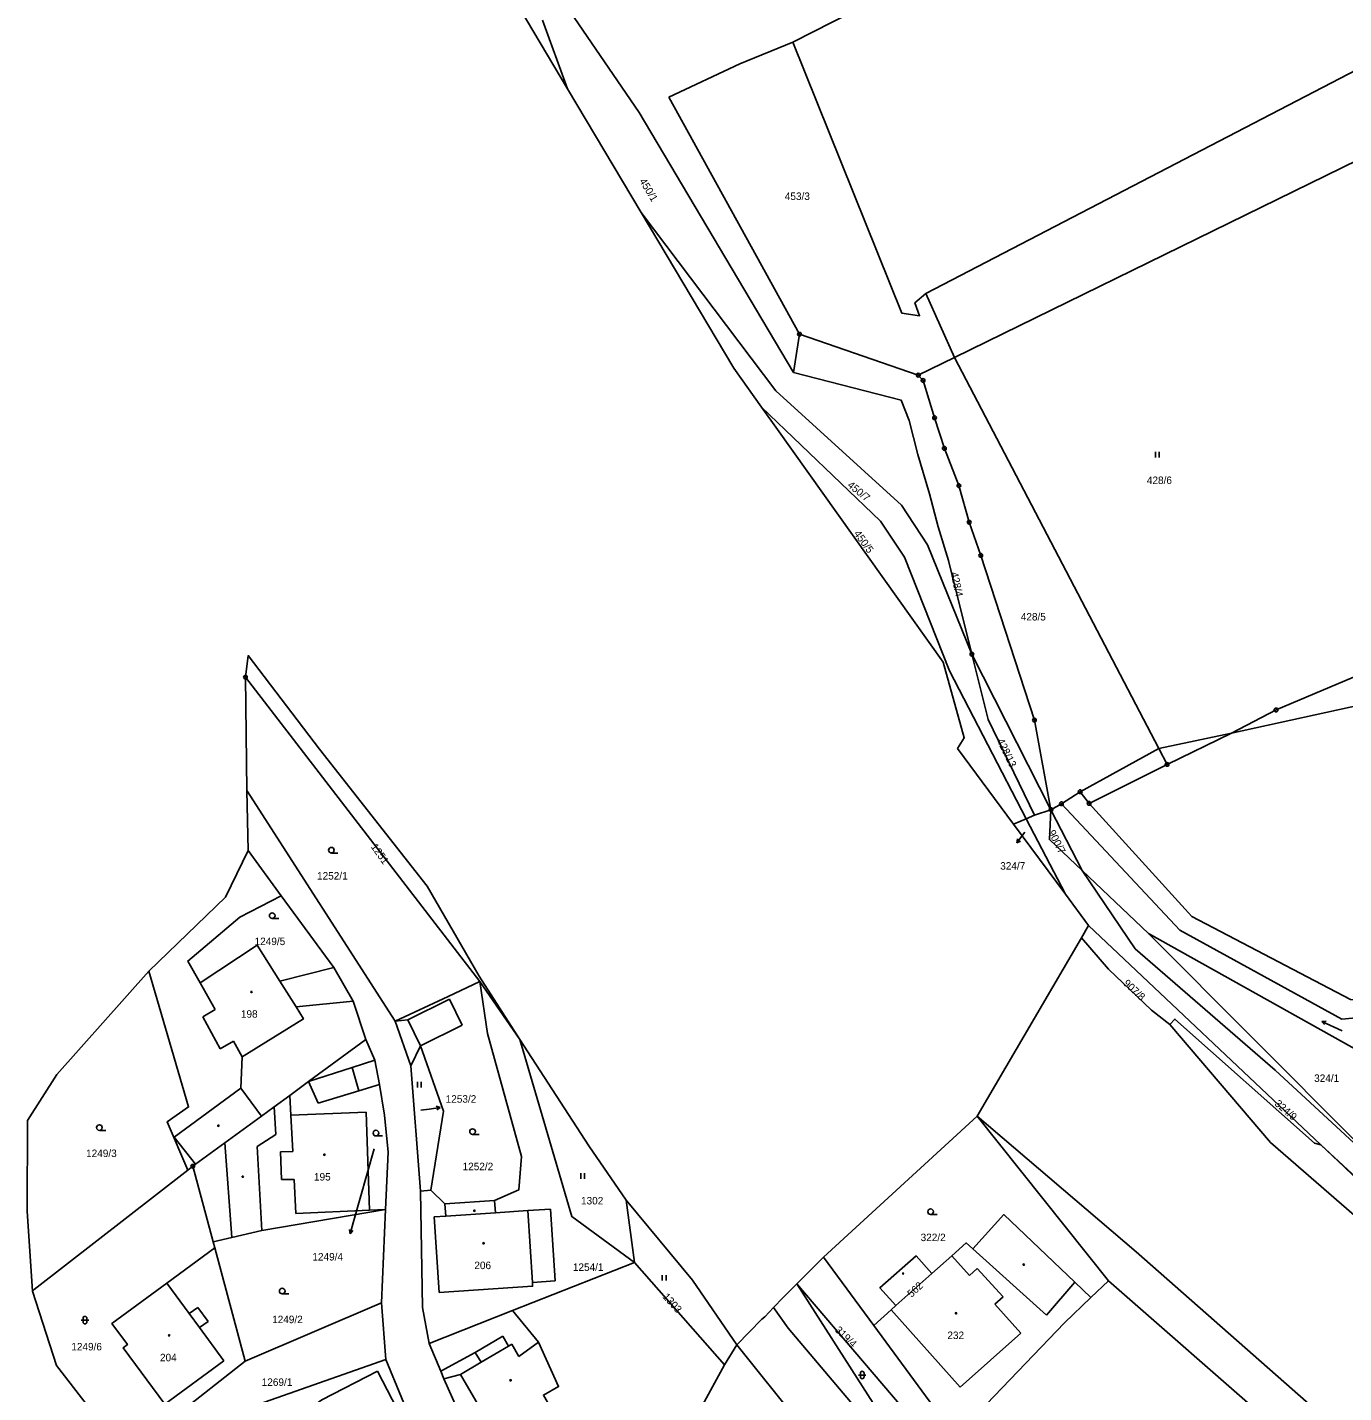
# Model space of a CAD drawing. Extents: x -745926 to -742978, y -968282 to -965689.
# Drawn here: x -745352.5 to -745176.7, y -966916.9 to -966734.5 of the extents above; entities that cross this region are included whole.
import ezdxf

# ---------------------------------------------------------------- set-up
doc = ezdxf.new("R2010")
doc.units = 0
for name, color, linetype in [('Hranice parcel', 7, 'Continuous'), ('Parcelní čísla', 7, 'Continuous'), ('Pop  PČ popisy', 7, 'Continuous'), ('Poz předměty', 7, 'Continuous'), ('Vnitřní kresba', 7, 'Continuous'), ('Značky bodu BP', 7, 'Continuous'), ('Značky budov', 7, 'Continuous'), ('Značky kultur', 7, 'Continuous')]:
    doc.layers.add(name, color=color, linetype=linetype)

msp = doc.modelspace()

# ---------------------------------------------------------------- linework, layer by layer
at = {"layer": 'Hranice parcel'}
for p, q in [((-745232.51, -966770.07), (-745145.82, -966725.01)), ((-745280.38, -966742.7), (-745289.63, -966727.14)), ((-745283.72, -966733.52), (-745280.38, -966742.7)), ((-745280.38, -966742.7), (-745270.55, -966759.22)), ((-745249.4, -966775.5), (-745266.84, -966743.81)), ((-745232.51, -966770.07), (-745228.69, -966778.6)), ((-745249.4, -966775.5), (-745250.2, -966780.6)), ((-745233.52, -966780.96), (-745249.4, -966775.5)), ((-745228.69, -966778.6), (-745233.52, -966780.96)), ((-745252.34, -966788.23), (-745254.48, -966785.22)), ((-745232.31, -966803.64), (-745226.36, -966818.23)), ((-745226.36, -966818.23), (-745215.8, -966839)), ((-745323.4, -966821.3), (-745292.08, -966861.94)), ((-745323.4, -966821.3), (-745323.2, -966836.46)), ((-745219.1, -966840.21), (-745229.35, -966820.44)), ((-745220.81, -966840.92), (-745228.28, -966830.83)), ((-745200.3, -966832.96), (-745210.7, -966838.16)), ((-745323.2, -966836.46), (-745303.39, -966867.27)), ((-745323.2, -966836.46), (-745323.04, -966844.47)), ((-745214.4, -966838.2), (-745211.9, -966836.6)), ((-745211.9, -966836.6), (-745210.7, -966838.16)), ((-745219.1, -966840.21), (-745218.01, -966839.75)), ((-745218.01, -966839.75), (-745215.8, -966839)), ((-745215.8, -966839), (-745214.4, -966838.2)), ((-745215.8, -966839), (-745211.62, -966847.14)), ((-745220.81, -966840.92), (-745219.1, -966840.21)), ((-745213.87, -966850.28), (-745220.81, -966840.92)), ((-745213.87, -966850.28), (-745219.1, -966840.21)), ((-745318.62, -966850.49), (-745323.04, -966844.47)), ((-745202.76, -966855.54), (-745211.62, -966847.14)), ((-745211.62, -966847.14), (-745204.57, -966857.59)), ((-745210.77, -966854.47), (-745213.87, -966850.28)), ((-745211.73, -966856.11), (-745225.67, -966879.96)), ((-745210.77, -966854.47), (-745211.73, -966856.11)), ((-745179.76, -966883.79), (-745210.77, -966854.47)), ((-745167.54, -966875.26), (-745202.76, -966855.54)), ((-745292.08, -966861.94), (-745286.75, -966869.71)), ((-745303.39, -966867.27), (-745301.3, -966873.2)), ((-745301.3, -966873.2), (-745300.03, -966889.97)), ((-745225.67, -966879.96), (-745246.2, -966898.77)), ((-745208.11, -966901.93), (-745225.67, -966879.96)), ((-745179.76, -966883.79), (-745180.6, -966883.53)), ((-745166.58, -966896), (-745179.76, -966883.79)), ((-745331.09, -966887.14), (-745330.43, -966886.63)), ((-745330.43, -966886.63), (-745327.71, -966896.73)), ((-745300.03, -966889.97), (-745298.65, -966889.82)), ((-745298.65, -966889.82), (-745296.74, -966891.65)), ((-745305.22, -966904.86), (-745304.68, -966892.41)), ((-745290.11, -966891.2), (-745296.74, -966891.65)), ((-745271.45, -966899.49), (-745272.52, -966891.18)), ((-745327.71, -966896.73), (-745327.5, -966897.54)), ((-745323.44, -966912.67), (-745327.5, -966897.54)), ((-745287.72, -966905.92), (-745271.45, -966899.49)), ((-745259.41, -966913.16), (-745271.45, -966899.49)), ((-745246.2, -966898.77), (-745249.76, -966902.34)), ((-745239.47, -966907.89), (-745246.2, -966898.77)), ((-745231.7, -966900.95), (-745236.51, -966905.25)), ((-745249.76, -966902.34), (-745237.49, -966921.45)), ((-745249.76, -966902.34), (-745234.53, -966920.19)), ((-745208.11, -966901.93), (-745210.46, -966904.18)), ((-745180.55, -966926.05), (-745208.11, -966901.93)), ((-745323.44, -966912.67), (-745305.22, -966904.86)), ((-745305.22, -966904.86), (-745304.66, -966912.43)), ((-745287.72, -966905.92), (-745298.84, -966910.32)), ((-745239.47, -966907.89), (-745228.55, -966922.71)), ((-745257.76, -966910.48), (-745259.41, -966913.16)), ((-745233, -966941.3), (-745257.76, -966910.48)), ((-745332.81, -966920.07), (-745323.44, -966912.67)), ((-745259.41, -966913.16), (-745274.6, -966940.8))]:
    msp.add_line(p, q, dxfattribs=at)
for points in [[(-745163.29, -966688.08), (-745207.73, -966714.8), (-745250.26, -966736.5)], [(-745250.2, -966780.6), (-745270.8, -966745.89), (-745287.59, -966721.28)], [(-745266.84, -966743.81), (-745257.34, -966739.37), (-745250.26, -966736.5)], [(-745250.26, -966736.5), (-745235.74, -966772.67), (-745233.34, -966773.02), (-745234, -966771.3), (-745232.51, -966770.07)], [(-745254.48, -966785.22), (-745258.18, -966780.03), (-745270.55, -966759.22)], [(-745270.55, -966759.22), (-745252.54, -966783.04), (-745235.77, -966798.31), (-745232.31, -966803.64)], [(-745200.3, -966832.96), (-745201.41, -966830.84), (-745228.69, -966778.6)], [(-745250.2, -966780.6), (-745235.8, -966784.3), (-745234.72, -966787), (-745233.57, -966791.57), (-745232.04, -966796.79), (-745230.89, -966801.2), (-745229.51, -966805.7), (-745226.36, -966818.23)], [(-745215.8, -966839), (-745218.01, -966827.04), (-745225.18, -966805.03), (-745226.72, -966800.61), (-745228.1, -966795.72), (-745230.04, -966790.74), (-745231.35, -966786.64), (-745232.89, -966781.66), (-745233.52, -966780.96)], [(-745229.35, -966820.44), (-745235.36, -966805.29), (-745238.55, -966800.45), (-745254.48, -966785.22)], [(-745228.28, -966830.83), (-745227.38, -966829.4), (-745230.21, -966819.31), (-745252.34, -966788.23)], [(-745286.75, -966869.71), (-745292.18, -966861.26), (-745299.11, -966849.23), (-745313.51, -966830.92), (-745323.01, -966818.42), (-745323.4, -966821.3)], [(-745226.36, -966818.23), (-745224.17, -966826.96), (-745218.01, -966839.75)], [(-745169.4, -966818.77), (-745185.74, -966825.68), (-745191.7, -966828.8), (-745200.3, -966832.96)], [(-745215.8, -966839), (-745216, -966843), (-745211.62, -966847.14)], [(-745214.4, -966838.2), (-745198.59, -966855.11), (-745176.97, -966866.98), (-745158.86, -966865.27)], [(-745210.7, -966838.16), (-745196.97, -966853.29), (-745175.81, -966864.35), (-745142.14, -966865.81), (-745134.77, -966866.14)], [(-745323.04, -966844.47), (-745326.06, -966850.68), (-745336.32, -966860.58)], [(-745321.26, -966879.92), (-745324, -966876.18), (-745323.82, -966872.03), (-745315.64, -966866.94), (-745316.64, -966865.35), (-745318.79, -966861.92), (-745321.82, -966857.1), (-745329.44, -966862.14), (-745331.1, -966859.23), (-745324.15, -966853.34), (-745318.62, -966850.49)], [(-745307.31, -966869.72), (-745309, -966864.6), (-745311.59, -966860.07), (-745318.62, -966850.49)], [(-745180.6, -966883.53), (-745199.24, -966866.97), (-745199.92, -966867.71), (-745202.37, -966865.76), (-745208.1, -966860.3), (-745211.73, -966856.11)], [(-745204.57, -966857.59), (-745185.85, -966873.79), (-745163.08, -966894.85), (-745158.2, -966898.34)], [(-745336.32, -966860.58), (-745348.59, -966874.36), (-745352.52, -966880.53)], [(-745336.32, -966860.58), (-745330.98, -966878.7), (-745333.83, -966880.68), (-745331.09, -966887.14)], [(-745303.39, -966867.27), (-745296.33, -966863.94), (-745292.08, -966861.94)], [(-745290.11, -966891.2), (-745286.86, -966889.77), (-745286.5, -966885.31), (-745291.07, -966868.91), (-745292.08, -966861.94)], [(-745307.31, -966869.72), (-745314.98, -966875.33), (-745317.48, -966877.16)], [(-745304.68, -966892.41), (-745304.34, -966884.77), (-745304.83, -966879.81), (-745305.5, -966875.7), (-745306.13, -966872.47), (-745307.31, -966869.72)], [(-745301.3, -966873.2), (-745299.99, -966870.53), (-745296.94, -966879.27), (-745298.65, -966889.82)], [(-745271.45, -966899.49), (-745279.8, -966893.35), (-745286.75, -966869.71)], [(-745272.52, -966891.18), (-745277.53, -966883.91), (-745286.75, -966869.71)], [(-745317.48, -966877.16), (-745319.56, -966878.68), (-745321.26, -966879.92)], [(-745304.68, -966892.41), (-745306.84, -966892.5), (-745307.29, -966879.41), (-745317.34, -966879.81), (-745317.48, -966877.16)], [(-745321.26, -966879.92), (-745326.15, -966883.5), (-745330.08, -966886.36), (-745330.43, -966886.63)], [(-745352.52, -966880.53), (-745352.53, -966892.61), (-745351.83, -966903.32)], [(-745140.63, -966918.06), (-745162.42, -966900.43), (-745176.65, -966886.73), (-745179.76, -966883.79)], [(-745351.83, -966903.32), (-745351.61, -966903.1), (-745331.09, -966887.14)], [(-745300.03, -966889.97), (-745299.73, -966905.49), (-745298.84, -966910.32)], [(-745327.71, -966896.73), (-745325.19, -966896.14), (-745321.2, -966895.19), (-745304.68, -966892.41)], [(-745296.74, -966891.65), (-745296.63, -966893.29), (-745298.18, -966893.4), (-745297.5, -966903.49), (-745285.04, -966902.65), (-745285.07, -966902.15), (-745285.67, -966892.55), (-745290, -966892.85), (-745290.11, -966891.2)], [(-745257.76, -966910.48), (-745263.7, -966901.85), (-745272.52, -966891.18)], [(-745210.46, -966904.18), (-745212.61, -966902.13), (-745222.1, -966893.08), (-745226.23, -966897.66), (-745227.12, -966896.86), (-745229.05, -966898.59), (-745231.7, -966900.95)], [(-745327.5, -966897.54), (-745333.89, -966902.25), (-745341.22, -966907.64), (-745339.15, -966910.46), (-745339.71, -966910.87), (-745334.15, -966918.42), (-745332.81, -966920.07)], [(-745236.51, -966905.25), (-745238.64, -966902.87), (-745233.8, -966898.61), (-745231.7, -966900.95)], [(-745351.83, -966903.32), (-745348.62, -966913.24), (-745339.35, -966925.23)], [(-745249.76, -966902.34), (-745251.2, -966903.8), (-745251.55, -966904.17), (-745252.87, -966905.5), (-745254, -966906.76), (-745254.4, -966907.06), (-745257.76, -966910.48)], [(-745236.51, -966905.25), (-745237.13, -966905.8), (-745239.47, -966907.89)], [(-745228.55, -966922.71), (-745214, -966907.56), (-745210.46, -966904.18)], [(-745296.89, -966915.01), (-745294.69, -966914.43), (-745289.63, -966923.08), (-745282.55, -966918.97), (-745283.6, -966917.2), (-745281.57, -966916.07), (-745284.25, -966910.15), (-745287.72, -966905.92)], [(-745298.84, -966910.32), (-745297.3, -966914), (-745296.89, -966915.01)], [(-745304.66, -966912.43), (-745325.66, -966919.82), (-745328.98, -966921.69), (-745330.87, -966923.57)], [(-745297.73, -966925.14), (-745300.47, -966922.59), (-745304.66, -966912.43)], [(-745305.75, -966913.99), (-745313.18, -966917.83), (-745314.95, -966919.14), (-745318.93, -966921.21), (-745315.33, -966927.53), (-745311.51, -966925.53), (-745307.15, -966926.1), (-745301.15, -966922.87), (-745305.75, -966913.99)], [(-745296.89, -966915.01), (-745295, -966919.3), (-745292.7, -966924.7), (-745284.5, -966933.2), (-745279.6, -966937.3), (-745274.6, -966940.8)]]:
    msp.add_lwpolyline(points, dxfattribs=at)
at = {"layer": 'Pop  PČ popisy'}
for p, q in [((-745219.47, -966842.23), (-745220.35, -966843.44)), ((-745220.35, -966843.44), (-745220.26, -966842.89)), ((-745220.35, -966843.44), (-745219.85, -966843.19)), ((-745219.3, -966842), (-745219.47, -966842.23)), ((-745299.97, -966879.14), (-745298.86, -966878.99)), ((-745298.86, -966878.99), (-745297.37, -966878.78)), ((-745297.37, -966878.78), (-745297.91, -966878.6)), ((-745297.37, -966878.78), (-745297.83, -966879.1)), ((-745306.18, -966884.32), (-745308.99, -966894.2)), ((-745308.99, -966894.2), (-745309.4, -966895.64)), ((-745309.4, -966895.64), (-745309.51, -966895.09)), ((-745309.4, -966895.64), (-745309.03, -966895.23))]:
    msp.add_line(p, q, dxfattribs=at)
at = {"layer": 'Poz předměty'}
for p, q in [((-745250.92, -966908.25), (-745252.87, -966905.5)), ((-745236.31, -966925.45), (-745250.92, -966908.25))]:
    msp.add_line(p, q, dxfattribs=at)
at = {"layer": 'Vnitřní kresba'}
for p, q in [((-745228.69, -966778.6), (-745140.59, -966735.47)), ((-745166.9, -966823.35), (-745191.7, -966828.8)), ((-745201.41, -966830.84), (-745191.7, -966828.8)), ((-745201.41, -966830.84), (-745211.9, -966836.6)), ((-745174.85, -966883.56), (-745202.76, -966855.54)), ((-745318.79, -966861.92), (-745311.59, -966860.07)), ((-745327.42, -966865.7), (-745329.44, -966862.14)), ((-745309, -966864.6), (-745316.64, -966865.35)), ((-745301.7, -966867.07), (-745296.15, -966864.31)), ((-745296.15, -966864.31), (-745294.43, -966867.78)), ((-745329.09, -966866.65), (-745327.42, -966865.7)), ((-745326.79, -966870.96), (-745329.09, -966866.65)), ((-745303.39, -966867.27), (-745301.7, -966867.07)), ((-745299.99, -966870.53), (-745301.7, -966867.07)), ((-745294.43, -966867.78), (-745299.99, -966870.53)), ((-745186.49, -966883.45), (-745199.92, -966867.71)), ((-745325, -966869.94), (-745326.79, -966870.96)), ((-745323.82, -966872.03), (-745325, -966869.94)), ((-745309.16, -966873.45), (-745306.13, -966872.47)), ((-745314.98, -966875.33), (-745309.16, -966873.45)), ((-745308.24, -966876.55), (-745309.16, -966873.45)), ((-745324, -966876.18), (-745332.9, -966882.74)), ((-745313.7, -966878.2), (-745314.98, -966875.33)), ((-745305.5, -966875.7), (-745308.24, -966876.55)), ((-745308.24, -966876.55), (-745313.7, -966878.2)), ((-745319.56, -966878.68), (-745319.35, -966882.41)), ((-745317.08, -966884.66), (-745317.34, -966879.81)), ((-745225.67, -966879.96), (-745204.42, -966898.08)), ((-745332.9, -966882.74), (-745330.08, -966886.36)), ((-745325.19, -966896.14), (-745326.15, -966883.5)), ((-745319.35, -966882.41), (-745321.85, -966884.01)), ((-745186.49, -966883.45), (-745157.85, -966908.35)), ((-745321.85, -966884.01), (-745321.2, -966895.19)), ((-745318.69, -966884.69), (-745317.08, -966884.66)), ((-745318.6, -966888.39), (-745318.69, -966884.69)), ((-745316.89, -966888.41), (-745318.6, -966888.39)), ((-745316.65, -966892.92), (-745316.89, -966888.41)), ((-745306.84, -966892.5), (-745316.65, -966892.92)), ((-745285.67, -966892.55), (-745282.65, -966892.35)), ((-745282.65, -966892.35), (-745282.01, -966901.94)), ((-745296.63, -966893.29), (-745290, -966892.85)), ((-745226.23, -966897.66), (-745216.42, -966906.53)), ((-745204.42, -966898.08), (-745178.07, -966921.24)), ((-745229.05, -966898.59), (-745226.69, -966901.23)), ((-745226.69, -966901.23), (-745225.65, -966900.3)), ((-745225.65, -966900.3), (-745222.2, -966904.06)), ((-745333.89, -966902.25), (-745330.89, -966906.31)), ((-745282.01, -966901.94), (-745285.07, -966902.15)), ((-745216.42, -966906.53), (-745212.61, -966902.13)), ((-745330.89, -966906.31), (-745329.77, -966905.48)), ((-745329.77, -966905.48), (-745328.39, -966907.35)), ((-745222.2, -966904.06), (-745223.29, -966905.03)), ((-745223.29, -966905.03), (-745219.83, -966908.91)), ((-745330.89, -966906.31), (-745329.52, -966908.18)), ((-745227.91, -966916.13), (-745237.13, -966905.8)), ((-745328.39, -966907.35), (-745329.52, -966908.18)), ((-745329.52, -966908.18), (-745326.26, -966912.61)), ((-745219.83, -966908.91), (-745227.91, -966916.13)), ((-745292.7, -966911.49), (-745289.02, -966909.34)), ((-745291.93, -966912.81), (-745288.25, -966910.66)), ((-745289.02, -966909.34), (-745288.25, -966910.66)), ((-745288.25, -966910.66), (-745287.82, -966910.41)), ((-745287.82, -966910.41), (-745286.86, -966912.05)), ((-745286.86, -966912.05), (-745284.25, -966910.15)), ((-745326.26, -966912.61), (-745334.15, -966918.42)), ((-745297.3, -966914), (-745292.7, -966911.49)), ((-745294.69, -966914.43), (-745291.93, -966912.81)), ((-745292.7, -966911.49), (-745291.93, -966912.81))]:
    msp.add_line(p, q, dxfattribs=at)
at = {"layer": 'Značky bodu BP'}
for centre, radius in [((-745249.4, -966775.5), 0.25), ((-745249.4, -966775.5), 0.0152), ((-745233.52, -966780.96), 0.25), ((-745233.52, -966780.96), 0.0152), ((-745232.89, -966781.66), 0.25), ((-745232.89, -966781.66), 0.0152), ((-745231.35, -966786.64), 0.25), ((-745231.35, -966786.64), 0.0152), ((-745230.04, -966790.74), 0.25), ((-745230.04, -966790.74), 0.0152), ((-745228.1, -966795.72), 0.25), ((-745228.1, -966795.72), 0.0152), ((-745226.72, -966800.61), 0.25), ((-745226.72, -966800.61), 0.0152), ((-745225.18, -966805.03), 0.25), ((-745225.18, -966805.03), 0.0152), ((-745226.36, -966818.23), 0.25), ((-745226.36, -966818.23), 0.0152), ((-745323.4, -966821.3), 0.25), ((-745323.4, -966821.3), 0.0152), ((-745218.01, -966827.04), 0.25), ((-745218.01, -966827.04), 0.0152), ((-745185.74, -966825.68), 0.25), ((-745185.74, -966825.68), 0.0152), ((-745200.3, -966832.96), 0.25), ((-745200.3, -966832.96), 0.0152), ((-745214.4, -966838.2), 0.25), ((-745211.9, -966836.6), 0.25), ((-745211.9, -966836.6), 0.0152), ((-745210.7, -966838.16), 0.25), ((-745215.8, -966839), 0.25), ((-745215.8, -966839), 0.0152), ((-745214.4, -966838.2), 0.0152), ((-745210.7, -966838.16), 0.0152), ((-745330.43, -966886.63), 0.25), ((-745330.43, -966886.63), 0.0152)]:
    msp.add_circle(centre, radius, dxfattribs=at)
at = {"layer": 'Značky budov'}
for centre in [(-745322.59, -966863.34), (-745327, -966881.22), (-745312.85, -966885.09), (-745323.75, -966888.02), (-745292.81, -966892.57), (-745291.59, -966896.92), (-745219.44, -966899.77), (-745235.54, -966900.96), (-745228.47, -966906.26), (-745333.58, -966909.23), (-745287.98, -966915.21)]:
    msp.add_circle(centre, 0.0875, dxfattribs=at)
at = {"layer": 'Značky kultur'}
for p, q in [((-745201.83, -966791.95), (-745201.83, -966791.2)), ((-745201.33, -966791.95), (-745201.33, -966791.2)), ((-745311.92, -966844.79), (-745311.04, -966844.79)), ((-745319.82, -966853.54), (-745318.94, -966853.54)), ((-745179.61, -966867.28), (-745179.06, -966867.26)), ((-745176.89, -966868.55), (-745179.61, -966867.28)), ((-745179.61, -966867.28), (-745179.27, -966867.71)), ((-745300.41, -966876.1), (-745300.41, -966875.35)), ((-745299.91, -966876.1), (-745299.91, -966875.35)), ((-745342.9, -966881.85), (-745342.02, -966881.85)), ((-745305.96, -966882.58), (-745305.08, -966882.58)), ((-745293.06, -966882.38), (-745292.18, -966882.38)), ((-745278.61, -966888.31), (-745278.61, -966887.56)), ((-745278.1, -966888.31), (-745278.1, -966887.56)), ((-745231.88, -966893.08), (-745231, -966893.08)), ((-745267.72, -966901.91), (-745267.72, -966901.16)), ((-745267.21, -966901.91), (-745267.21, -966901.16)), ((-745318.48, -966903.68), (-745317.6, -966903.68)), ((-745345.33, -966907.18), (-745344.33, -966907.18)), ((-745345.08, -966906.93), (-745345.08, -966907.43)), ((-745344.58, -966907.43), (-745344.58, -966906.93)), ((-745241.51, -966914.52), (-745240.51, -966914.52)), ((-745241.26, -966914.27), (-745241.26, -966914.77)), ((-745240.76, -966914.77), (-745240.76, -966914.27))]:
    msp.add_line(p, q, dxfattribs=at)
for centre in [(-745311.92, -966844.41), (-745319.82, -966853.16), (-745342.9, -966881.47), (-745293.06, -966882), (-745305.96, -966882.2), (-745231.88, -966892.7), (-745318.48, -966903.3)]:
    msp.add_circle(centre, 0.375, dxfattribs=at)
for centre, start, end in [((-745344.83, -966906.93), 0, 180), ((-745344.83, -966907.43), 180, 359.9879), ((-745241.01, -966914.27), 0, 180), ((-745241.01, -966914.77), 180, 359.9879)]:
    msp.add_arc(centre, 0.25, start, end, dxfattribs=at)

# ---------------------------------------------------------------- texts
at = {"layer": 'Parcelní čísla'}
for s, rotation, p in [('450/1', 301, (-745270.83, -966755.02)), ('450/7', 321, (-745243.07, -966795.8)), ('450/5', 306, (-745242.18, -966802.14)), ('428/4', 282, (-745229.2, -966807.37)), ('428/13', 296, (-745223.04, -966829.78)), ('900/7', 297, (-745216.2, -966842.02)), ('1251', 305, (-745306.69, -966843.96)), ('907/8', 317, (-745206.23, -966862.3)), ('324/9', 319, (-745186.01, -966878.4)), ('1303', 312, (-745267.74, -966904.11)), ('562', 43, (-745234.43, -966904.22)), ('319/4', 316, (-745244.74, -966908.6))]:
    msp.add_text(s, height=1, rotation=rotation, dxfattribs=at).set_placement(p)
for s, p in [('453/3', (-745251.35, -966757.56)), ('428/6', (-745202.99, -966795.5)), ('428/5', (-745219.83, -966813.73)), ('324/7', (-745222.58, -966847.01)), ('1252/1', (-745313.83, -966848.34)), ('1249/5', (-745322.17, -966857.09)), ('198', (-745324, -966866.79)), ('324/1', (-745180.65, -966875.37)), ('1253/2', (-745296.65, -966878.14)), ('1249/3', (-745344.68, -966885.4)), ('1252/2', (-745294.39, -966887.16)), ('195', (-745314.24, -966888.54)), ('1302', (-745278.57, -966891.73)), ('322/2', (-745233.21, -966896.63)), ('1249/4', (-745314.45, -966899.22)), ('206', (-745292.82, -966900.37)), ('1254/1', (-745279.66, -966900.61)), ('1249/2', (-745319.83, -966907.59)), ('232', (-745229.64, -966909.71)), ('1249/6', (-745346.65, -966911.23)), ('204', (-745334.81, -966912.68)), ('1269/1', (-745321.22, -966915.97))]:
    msp.add_text(s, height=1, dxfattribs=at).set_placement(p)

doc.saveas('drawing.dxf')
